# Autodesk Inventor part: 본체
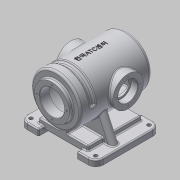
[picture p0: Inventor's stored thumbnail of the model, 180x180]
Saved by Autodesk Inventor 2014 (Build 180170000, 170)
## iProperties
Created: 2015-10
Part Number: 본체
Document SubType Name: Modeling
Designer: mdu
Density: 2.71 g/cm^3
Material: 알루미늄 6061
Mass: 4592.12 g
Surface Area: 2715.66 cm^2
Volume: 1694.51 cm^3
Appearance: 기본값(1)
Author: mdu
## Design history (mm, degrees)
sketch "스케치1"
  geometry: L1 (-100, 85)-(-50, 85); L2 (-50, 85)-(-50, -85); L3 (-50, -85)-(-100, -85); L4 (-100, -85)-(-100, 85); L5 (50, 85)-(100, 85); L6 (100, 85)-(100, -85); L7 (100, -85)-(50, -85); L8 (50, -85)-(50, 85); 3 further points
  constraints: 16 end point, 4 parallel, 2 equal length, 2 horizontal, 2 horizontal alignment, 2 midpoint, 2 perpendicular
  dimensions: "d0" = 100 distance between parallel lines of L8 L2; "d1" = 170 distance of L3.end L1.start; "d3" = 200 distance between parallel lines of L6 L4; "d4" = 50 distance from line of point (0, 0) L2 (= 0.5 x d0)
extrude "돌출1" new body sketch "스케치1" distance "d5" = 16; taper "d6" = 0 deg
node "작업 평면1"
sketch "스케치2"
  geometry: L1 (-65, 70)-(65, 70); L2 (65, 70)-(65, -70); L3 (65, -70)-(-65, -70); L4 (-65, -70)-(-65, 70); 3 further points
  constraints: 8 end point, 2 midpoint, 2 parallel, 1 horizontal, 1 horizontal alignment, 1 perpendicular, 1 vertical alignment
  dimensions: "d8" = 130 distance of L2.end L3.end; "d9" = 140 distance of L1.end L2.end
extrude "돌출2" join sketch "스케치2" distance "d10" = 20; taper "d11" = 0 deg
sketch "스케치3"
  geometry: L1 (-100, 110)-(100, 110); L2 (85, 0)-(-85, 0) reference; L3 (100, 110)-(100, 175); L4 (100, 175)-(-90, 175); L5 (-90, 175)-(-90, 156); L6 (-90, 156)-(-100, 156); L7 (-100, 156)-(-100, 110); L8 (90, 110)-(90, 165); L9 (90, 165)-(-75, 165); L10 (-75, 165)-(-75, 110); L11 (-100, 142.5)-(-75, 142.5); 3 further points
  constraints: 20 end point, 5 perpendicular, 4 parallel, 4 point on line, 2 midpoint, 1 horizontal, 1 vertical alignment
  dimensions: "d12" = 110 distance from line of L2 L1.end; "d13" = 200 distance of L1.start L1.end; "d14" = 130 diameter of L4 L1; "d15" = 92 diameter of L6 L1; "d16" = 10 distance of L5.end L6.end; "d42" = 110 diameter of L9 L1; "d43" = 10 distance between parallel lines of L3 L8; "d44" = 25 distance between parallel lines of L10 L7; "d45" = 65 diameter of L11 L1
revolve "회전1" sketch "스케치3" stored, may be unused: angle "d17" = 90 deg
sketch "스케치4"
  geometry: L1 (-50, 70)-(50, 70) reference; L2 (50, -70)-(-50, -70) reference; L3 (-10, 70)-(-10, -70); L4 (10, -70)-(10, 70); 1 further point
  constraints: 4 end point, 4 point on line, 2 perpendicular
  dimensions: "d18" = 20 distance between parallel lines of L4 L3; "d19" = 10 distance from line of point (0, 0) L3
extrude "돌출3" join sketch "스케치4" stored distance "d20" = 10; taper "d21" = 0 deg
node "작업 평면2"
sketch "스케치5"
  geometry: L1 (-50, -8)-(0, -8) reference; L2 (100, -8)-(150, -8) reference; L3 (-40, -8)-(-8.943, -74.601); L4 (140, -8)-(108.943, -74.601); L5 (-50, 8)-(-50, -8) reference; L6 (150, 8)-(150, -8) reference; A1 r 65 centre (50, -102) between (-8.943, -74.601) and (108.943, -74.601) reference; 1 further point
  constraints: 4 end point, 2 point on circle, 2 point on line, 1 equal length
  dimensions: "d23" = 10 distance from line of L3.start L5; "d24" = 10 distance from line of L4.start L6; "d25" = 25 deg angle of L3 L5
feature "리브1" sketch "스케치5" dims "d26" = 1, "d27" = 20, "d28" = 0
node "작업 평면3"
sketch "스케치6"
  geometry: L1 (100, 156)-(100, 64) reference; C1 r 40 at (-25, 110); 2 further points
  constraints: 1 centre point, 1 horizontal alignment, 1 midpoint
  dimensions: "d37" = 80 diameter of C1; "d38" = 125 distance from line of C1.centre L1
extrude "돌출4" join sketch "스케치6" stored distance "d39" = 10; taper "d40" = 0 deg
hole "구멍1" diameter "d48" = 42; stored, may be unused: countersink angle "d52" = 90 deg, drill point angle "d54" = 118 deg; dims "d46" = 10, "d47" = 10, "d49" = 6, "d50" = 52, "d51" = 18, "d53" = 8
sketch "스케치7"
  geometry: C1 r 40 at (0, 0) reference; 2 further points
  constraints: 1 horizontal alignment
  dimensions: "d55" = 32.5 distance of point (32.5, 0) C1.centre
hole "구멍2" sketch "스케치7" at (32.5, 0) diameter "d56" = 3.242; stored, may be unused: countersink angle "d60" = 90 deg, drill point angle "d62" = 118 deg; dims "d57" = 11, "d58" = 52, "d59" = 18, "d61" = 13
sketch "스케치8"
  geometry: C1 r 46 at (0, 0) reference; 2 further points
  constraints: 1 vertical alignment
  dimensions: "d66" = 39 distance of C1.centre point (0, 39)
hole "구멍3" sketch "스케치8" at (0, 39) diameter "d67" = 3.242; stored, may be unused: countersink angle "d71" = 90 deg, drill point angle "d73" = 118 deg; dims "d68" = 11, "d69" = 52, "d70" = 18, "d72" = 13
fillet "모깎기7" dims "d77" = 20, "d78" = 5, "d79" = 3, "d80" = 10, "d107" = 10
fillet "모깎기8" dims "d81" = 3
fillet "모깎기9" dims "d82" = 3
fillet "모깎기10" dims "d83" = 3, "d84" = 0.3
chamfer "모따기1" distance "d85" = 1; stored, may be unused: second distance "d86" = 2, angle "d87" = 45 deg
node "작업 평면4"
sketch "스케치10"
  geometry: 5 further points
  constraints: 2 horizontal alignment, 2 vertical alignment
  dimensions: "d90" = 170 distance of point (85, 70) point (-85, 70); "d91" = 140 distance of point (-85, 70) point (-85, -70); "d92" = 70 vertical distance of point (0, 0) point (-85, -70) (= 0.5 x d91); "d93" = 85 horizontal distance of point (0, 0) point (-85, 70) (= 0.5 x d90)
hole "구멍4" sketch "스케치10" at (-85, 70), (85, 70), (85, -70), (-85, -70) diameter "d94" = 10; stored, may be unused: countersink angle "d98" = 90 deg, drill point angle "d100" = 118 deg; dims "d95" = 6, "d96" = 4, "d97" = 2, "d99" = 8
node "작업 평면5"
sketch "스케치12" dims "d22" = -90
  geometry: L1 (-65, -90)-(65, -90) reference; L2 (65, 85)-(-65, 85) reference; L3 (0, -90)-(0, 85); 3 further points
  constraints: 3 midpoint, 2 end point, 1 coincident, 1 other
feature "엠보싱3" sketch "스케치12" dims "d105" = 1, "d106" = 0
node "작업축1"
sketch "스케치13"
  geometry: L1 (-85, 175)-(90, 175) reference; L2 (-65, 175)-(-50, 175); L3 (-50, 175)-(-50, 170); L4 (-50, 170)-(-65, 170); L5 (-65, 170)-(-65, 175); L6 (-90, 50)-(-90, 170) reference; L7 (-140, 110)-(140, 110) reference; 1 further point
  constraints: 8 end point, 2 parallel, 1 horizontal, 1 perpendicular, 1 point on line
  dimensions: "d108" = 25 distance between parallel lines of L5 L6; "d109" = 15 distance of L3.end L4.end; "d110" = 5 distance of L2.end L3.end
revolve "회전2" sketch "스케치13" stored, may be unused: angle "d111" = 180 deg
fillet "모깎기11" dims "d112" = 5
fillet "모깎기12" dims "d113" = 5
fillet "모깎기13" dims "d114" = 3
node "솔리드1"
mirror "대칭1"
pattern_circular "원형 패턴1" dims angle "d64" = 360 deg
mirror "대칭3"
pattern_circular "원형 패턴2" dims angle "d75" = 360 deg
other parameters: "d7" = 8, "d36" = -75
